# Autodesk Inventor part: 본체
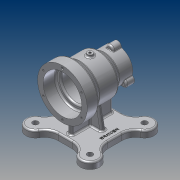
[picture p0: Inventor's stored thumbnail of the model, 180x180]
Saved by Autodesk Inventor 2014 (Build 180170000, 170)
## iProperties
Created: 2017-03
Part Number: 본체
Material: 알루미늄 6061
Document SubType Name: Modeling
Designer: Administrator
Density: 2.71 g/cm^3
Appearance: 알루미늄 - 평지
Mass: 997.337 g
Surface Area: 848.351 cm^2
Volume: 368.021 cm^3
Author: Administrator
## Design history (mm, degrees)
sketch "스케치1"
  geometry: L1 (-50, 0)-(50, 0); L2 (-50, 35)-(-50, 45); L3 (-50, 45)-(-30, 45); L4 (-30, 45)-(-19, 36); L5 (-19, 36)-(15, 36); L6 (15, 36)-(25.389, 27.5); L7 (25.389, 27.5)-(50, 27.5); L8 (50, 27.5)-(50, 17.5); L9 (50, 17.5)-(20, 17.5); L10 (20, 17.5)-(20, 26); L11 (20, 26)-(-27, 26); L12 (-27, 26)-(-27, 35); L13 (-27, 35)-(-50, 35); 2 further points
  constraints: 26 end point, 7 parallel, 2 horizontal, 2 perpendicular, 2 point on line, 1 coincident, 1 midpoint, 1 vertical
  dimensions: "d0" = 100 distance of L1.start L1.end; "d1" = 70 diameter of L13 L1; "d4" = 90 diameter of L3 L1; "d5" = 52 diameter of L11 L1; "d6" = 35 diameter of L9 L1; "d7" = 23 distance between parallel lines of L12 L2; "d9" = 72 diameter of L5 L1; "d10" = 55 diameter of L7 L1; "d11" = 20 distance from line of L3.end L2; "d12" = 31 distance from line of L2 L4.end; "d13" = 65 distance from line of L2 L5.end; "d15" = 30 distance between parallel lines of L10 L8; "d16" = 47 distance between parallel lines of L12 L10 (derived)
revolve "회전1" sketch "스케치1" stored, may be unused: angle "d17" = 90 deg
node "작업 평면1"
sketch "스케치2"
  geometry: L1 (-45, 45)-(45, 45); L2 (45, 45)-(45, -45); L3 (45, -45)-(-45, -45); L4 (-45, -45)-(-45, 45); L5 (-45, 45)-(45, -45); L6 (45, 45)-(-45, -45); L7 (0, 0)-(70, 0)
  constraints: 14 end point, 2 horizontal, 2 midpoint, 2 parallel, 1 perpendicular
  dimensions: "d19" = 90 distance of L2.end L3.end; "d20" = 90 distance of L1.end L2.end
extrude "돌출1" join sketch "스케치2" distance "d25" = 12; taper "d26" = 0 deg
sketch "스케치3"
  geometry: L1 (0, 0)-(-49.497, 49.497); L2 (0, 0)-(70, 0); L3 (-49.497, 49.497)-(-50.837, 50.837); L4 (-45, -45)-(-45, 45) reference; L5 (-45, 45)-(45, 45) reference; L6 (0, 0)-(49.497, 49.497); L7 (0, 0)-(70, 0); L8 (45, 45)-(45, -45) reference; L9 (0, 0)-(49.497, -49.497); L10 (45, -45)-(-45, -45) reference; L11 (45, -12.842)-(45, -45); L12 (12.842, -45)-(45, -45); A1 r 17 centre (49.497, 49.497) between (57.796, 34.661) and (34.661, 57.796); A2 r 25 centre (70, 12.842) between (57.796, 34.661) and (45, 12.842); A3 r 25 centre (12.842, 70) between (12.842, 45) and (34.661, 57.796); A4 r 17 centre (49.497, -49.497) between (57.796, -34.661) and (34.661, -57.796); A5 r 25 centre (70, -12.842) between (45, -12.842) and (57.796, -34.661); A6 r 25 centre (12.842, -70) between (34.661, -57.796) and (12.842, -45); 2 further points
  constraints: 17 end point, 12 point on circle, 9 tangent, 6 centre point, 3 coincident, 3 collinear, 3 point on line, 2 equal length, 2 horizontal, 2 perpendicular
  dimensions: "d28" = 70 distance of L1.start L1.end; "d29" = 135 deg angle of L2 L1; "d39" = 70 distance of L6.end L1.start; "d40" = 45 deg angle of L7 L6 (derived); "d41" = 34 diameter of A1; "d42" = 25 radius of A2; "d43" = 25 radius of A3; "d54" = 70 distance of L1.start L9.end; "d55" = 34 diameter of A4; "d56" = 25 radius of A5; "d57" = 25 radius of A6
extrude "돌출2" join sketch "스케치3" distance "d44" = 12; taper "d45" = 0 deg
hole "구멍1" sketch "스케치3" diameter "d46" = 10; stored, may be unused: countersink angle "d50" = 90 deg, drill point angle "d52" = 118 deg; dims "d47" = 6, "d48" = 4, "d49" = 2, "d51" = 8
hole "구멍2" diameter "d60" = 10; stored, may be unused: countersink angle "d64" = 90 deg, drill point angle "d66" = 118 deg; dims "d58" = 10, "d59" = 10, "d61" = 6, "d62" = 4, "d63" = 2, "d65" = 8
sketch "스케치5"
  geometry: L1 (-31.096, 18.14)-(-70, 25); L2 (-31.096, -18.14)-(-70, -25); L3 (-70, -34.661)-(-70, -12.842) reference; L4 (-70, 12.842)-(-70, 34.661) reference; L5 (-70, -34.661)-(-70, -66.497) reference; L6 (-70, 66.497)-(-70, 34.661) reference; L7 (-70, -12.842)-(-70, 12.842) reference; A1 r 36 centre (0, 0) between (-31.096, 18.14) and (-31.096, -18.14) reference; 3 further points
  constraints: 4 end point, 2 point on circle, 2 point on line
  dimensions: "d68" = 25 vertical distance of point (0, 0) L1.end; "d69" = 25 vertical distance of L2.end point (0, 0); "d70" = 100 deg angle of L5 L2; "d71" = 100 deg angle of L1 L6
extrude "돌출3" join sketch "스케치5" stored distance "d72" = 8; taper "d73" = 0 deg
sketch "스케치6"
  geometry: L1 (-19, -36)-(15, -36) reference; L2 (25.389, -27.5)-(50, -27.5) reference; L3 (15, -36)-(25.389, -27.5) reference; L4 (-30, -45)-(-19, -36) reference; L5 (-50, -45)-(-30, -45) reference; L6 (-12.842, -70)-(-34.661, -70) reference; L7 (12.842, -70)-(34.661, -70) reference; L8 (-66.497, -70)-(-34.661, -70) reference; L9 (66.497, -70)-(34.661, -70) reference; L10 (-37, -45)-(-37, -70); L11 (37, -70)-(37, -27.5); 3 further points
  constraints: 4 end point, 4 point on line, 1 parallel, 1 perpendicular
  dimensions: "d74" = 37 distance from line of point (0, 0) L10; "d75" = 37 distance from line of L11 point (0, 0)
feature "리브1" dims "d76" = 1, "d77" = 8, "d78" = 0, "d79" = 0, "d80" = 1, "d81" = 1
feature "리브2" dims "d82" = 1, "d83" = 8, "d84" = 0, "d85" = 0, "d86" = 1, "d87" = 1
sketch "스케치7"
  geometry: L1 (0, 0)-(0, 40); 1 further point
  constraints: 2 end point, 1 coincident, 1 vertical
  dimensions: "d88" = 40 distance of L1.start L1.end
hole "구멍3" sketch "스케치7" at (0, 40) diameter "d89" = 3.242; stored, may be unused: countersink angle "d93" = 90 deg, drill point angle "d95" = 118 deg; dims "d90" = 9, "d91" = 4, "d92" = 2, "d94" = 11
sketch "스케치8"
  geometry: A1 r 7 centre (0, 27.5) between (6.943, 26.609) and (-6.943, 26.609); A2 r 27.5 centre (0, 0) between (-6.943, 26.609) and (6.943, 26.609) reference; 1 further point
  constraints: 4 point on circle, 1 centre point, 1 vertical alignment
  dimensions: "d99" = 14 diameter of A1; "d100" = 27.5 distance of point (0, 0) A1.centre
extrude "돌출4" join sketch "스케치8" distance "d101" = 15; taper "d102" = 0 deg
hole "구멍4" diameter "d105" = 3.242; stored, may be unused: countersink angle "d109" = 90 deg, drill point angle "d111" = 118 deg; dims "d103" = 10, "d104" = 10, "d106" = 9, "d107" = 4, "d108" = 2, "d110" = 11
fillet "모깎기1" dims "d115" = 3
fillet "모깎기2" dims "d116" = 1
node "작업 평면2"
sketch "스케치9"
  geometry: C1 r 5 at (0, 0); 1 further point
  constraints: 1 centre point, 1 coincident
  dimensions: "d118" = 10 diameter of C1
extrude "돌출5" join sketch "스케치9" stored distance "d119" = 15; taper "d120" = 0 deg
hole "구멍5" diameter "d123" = 4.134; stored, may be unused: countersink angle "d127" = 90 deg, drill point angle "d129" = 118 deg; dims "d121" = 10, "d122" = 10, "d124" = 9, "d125" = 4, "d126" = 2, "d128" = 11
fillet "모깎기3" dims "d130" = 3
fillet "모깎기4" dims "d131" = 3
fillet "모깎기5" dims "d132" = 3
fillet "모깎기6" dims "d133" = 3
chamfer "모따기1" distance "d134" = 1; stored, may be unused: second distance "d135" = 2, angle "d136" = 45 deg
fillet "모깎기7" dims "d137" = 3
node "작업 평면3"
sketch "스케치10"
  geometry: 2 further points
  constraints: 1 vertical alignment, 1 other
  dimensions: "d139" = 35 distance of point (0, 0) point (0, -35)
feature "엠보싱1" sketch "스케치10" dims "d0" = 100, "d1" = 70, "d4" = 90, "d5" = 52, "d6" = 35, "d7" = 23, "d9" = 72, "d10" = 55, "d11" = 20, "d12" = 31, "d13" = 65, "d15" = 30, "d16" = 47 (derived), "d19" = 90, "d20" = 90, "d140" = 0.5, "d141" = 0
fillet "모깎기8" dims "d142" = 3
node "솔리드1"
mirror "대칭1"
pattern_circular "원형 패턴1" dims angle "d97" = 360 deg
pattern_circular "원형 패턴2" dims angle "d113" = 360 deg
other parameters: "d18" = -82
